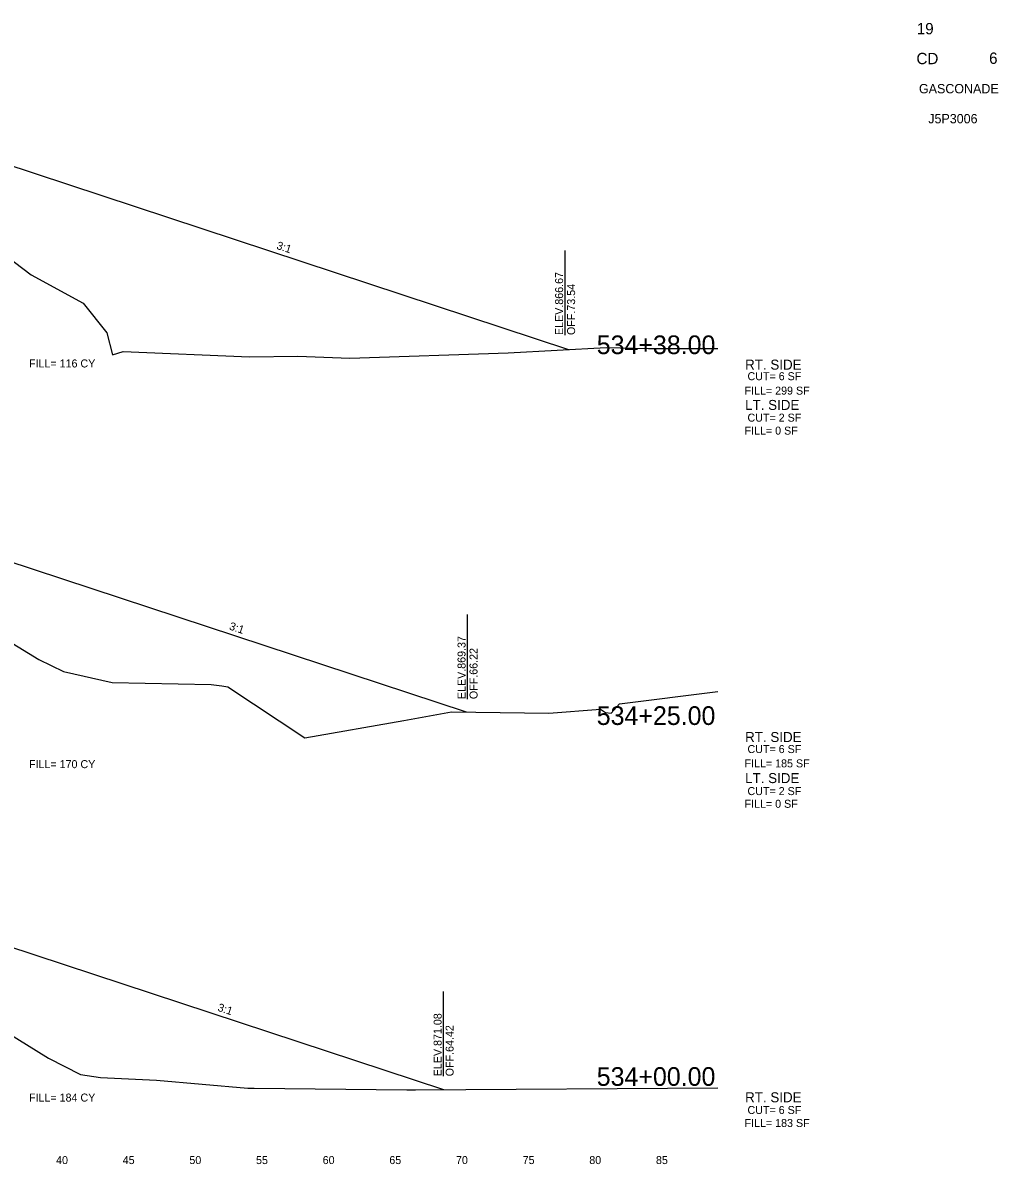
# Model space of a CAD drawing. Extents: x -4 to 359, y 0 to 1436.
# Drawn here: x 81 to 154.2, y 750.5 to 836.1 of the extents above; entities that cross this region are included whole.
import ezdxf

# ---------------------------------------------------------------- set-up
doc = ezdxf.new("R2010")
doc.units = 0
for name, color, linetype in [('Common-Title block info', 7, 'Continuous'), ('XS-Existing surface-ground', 7, 'Continuous'), ('XS-Proposed surface-ground', 7, 'Continuous'), ('XS-Text-ditch slope', 7, 'Continuous'), ('XS-Text-earthwork labels', 7, 'Continuous'), ('XS-Text-offset label', 7, 'Continuous'), ('XS-Text-profile report', 7, 'Continuous'), ('XS-Text-tie elevation', 7, 'Continuous'), ('XS-Text-tie offset', 7, 'Continuous')]:
    doc.layers.add(name, color=color, linetype=linetype)

msp = doc.modelspace()

# ---------------------------------------------------------------- linework, layer by layer
at = {"layer": 'XS-Existing surface-ground'}
for p, q in [((76.346, 821.105), (81.611, 817.179)), ((81.611, 817.179), (85.502, 815.044)), ((85.502, 815.044), (87.286, 812.818)), ((87.286, 812.818), (87.719, 811.17)), ((117.383, 811.308), (124.748, 811.723)), ((124.748, 811.723), (127.914, 811.633)), ((127.914, 811.633), (133.13, 811.634)), ((87.719, 811.17), (88.513, 811.42)), ((88.513, 811.42), (97.997, 811.011)), ((97.997, 811.011), (101.605, 811.078)), ((101.605, 811.078), (105.511, 810.922)), ((105.511, 810.922), (117.383, 811.308)), ((76.896, 791.548), (82.186, 788.316)), ((82.186, 788.316), (84.047, 787.406)), ((84.047, 787.406), (87.696, 786.585)), ((87.696, 786.585), (95.109, 786.45)), ((95.109, 786.45), (95.927, 786.35)), ((95.927, 786.35), (96.376, 786.272)), ((96.376, 786.272), (102.143, 782.455)), ((125.754, 785.002), (133.13, 785.912)), ((125.125, 784.286), (125.754, 785.002)), ((109.565, 783.737), (113.15, 784.398)), ((113.15, 784.398), (120.448, 784.284)), ((120.448, 784.284), (124.328, 784.604)), ((124.328, 784.604), (124.692, 784.349)), ((124.692, 784.349), (125.125, 784.286)), ((102.143, 782.455), (109.565, 783.737)), ((77.571, 761.715), (82.923, 758.416)), ((82.923, 758.416), (85.311, 757.202)), ((85.311, 757.202), (86.823, 756.97)), ((86.823, 756.97), (91.009, 756.771)), ((91.009, 756.771), (97.857, 756.162)), ((97.857, 756.162), (98.333, 756.171)), ((98.333, 756.171), (109.804, 756.046)), ((109.804, 756.046), (110.456, 756.045)), ((110.456, 756.045), (133.13, 756.197))]:
    msp.add_line(p, q, dxfattribs=at)
at = {"layer": 'XS-Proposed surface-ground'}
for points in [[(79.416, 825.593), (121.928, 811.564)], [(79.64, 795.8), (114.242, 784.381)], [(79.699, 766.901), (112.553, 756.059)]]:
    msp.add_lwpolyline(points, dxfattribs=at)
at = {"layer": 'XS-Text-tie offset'}
for p, q in [((121.666, 812.651), (121.666, 819.001)), ((114.348, 785.346), (114.348, 791.696)), ((112.553, 757.059), (112.553, 763.409))]:
    msp.add_line(p, q, dxfattribs=at)

# ---------------------------------------------------------------- texts
at = {"layer": 'Common-Title block info'}
for s, height, p in [('19', 0.85, (148.047, 835.203)), ('CD', 0.85, (148.025, 832.965)), ('6', 0.85, (153.472, 832.988)), ('GASCONADE', 0.7, (148.211, 830.778)), ('J5P3006', 0.7, (148.909, 828.528))]:
    msp.add_text(s, height=height, dxfattribs=at).set_placement(p)
at = {"layer": 'XS-Text-ditch slope'}
for p in [(99.97, 819.126), (96.423, 790.578), (95.555, 761.984)]:
    msp.add_text('3:1', height=0.6, rotation=341.73711, dxfattribs=at).set_placement(p)
at = {"layer": 'XS-Text-earthwork labels'}
for s, height, p in [('FILL= 116 CY           ', 0.6, (81.452, 810.221)), ('RT. SIDE', 0.75, (135.171, 810.058)), (' CUT= 6 SF           ', 0.6, (135.125, 809.264)), ('FILL= 299 SF           ', 0.6, (135.125, 808.182)), ('LT. SIDE', 0.75, (135.171, 807.034)), (' CUT= 2 SF           ', 0.6, (135.125, 806.157)), ('FILL= 0 SF           ', 0.6, (135.125, 805.183)), ('RT. SIDE', 0.75, (135.171, 782.129)), (' CUT= 6 SF           ', 0.6, (135.125, 781.301)), ('FILL= 170 CY           ', 0.6, (81.452, 780.17)), ('FILL= 185 SF           ', 0.6, (135.125, 780.227)), ('LT. SIDE', 0.75, (135.171, 779.048)), (' CUT= 2 SF           ', 0.6, (135.125, 778.149)), ('FILL= 0 SF           ', 0.6, (135.125, 777.197)), ('RT. SIDE', 0.75, (135.171, 755.111)), ('FILL= 184 CY           ', 0.6, (81.452, 755.164)), (' CUT= 6 SF           ', 0.6, (135.125, 754.233)), ('FILL= 183 SF           ', 0.6, (135.125, 753.258))]:
    msp.add_text(s, height=height, dxfattribs=at).set_placement(p)
at = {"layer": 'XS-Text-offset label'}
for s, height, p in [('           534+38.00           ', 1.4, (118.317, 811.221)), ('           534+25.00           ', 1.4, (118.317, 783.409)), ('           534+00.00           ', 1.4, (118.317, 756.344)), ('           40           ', 0.6, (81.03, 750.477)), ('           45           ', 0.6, (86.03, 750.477)), ('           50           ', 0.6, (91.03, 750.477)), ('           55           ', 0.6, (96.03, 750.477)), ('           60           ', 0.6, (101.03, 750.477)), ('           65           ', 0.6, (106.03, 750.477)), ('           70           ', 0.6, (111.03, 750.477)), ('           75           ', 0.6, (116.03, 750.477)), ('           80           ', 0.6, (121.03, 750.477)), ('           85           ', 0.6, (126.03, 750.477))]:
    msp.add_text(s, height=height, dxfattribs=at).set_placement(p)
at = {"layer": 'XS-Text-profile report'}
for s, p in [('Rt_Agg_Layer_1_B13', (82.896, 824.439)), ('Fill_Slope_2_B1', (121.916, 811.564)), ('Rt_Agg_Layer_1_B13', (83.12, 794.646)), ('Fill_Slope_2_B1', (114.23, 784.38)), ('Rt_Agg_Layer_1_B13', (83.179, 765.747)), ('Fill_Slope_2_B1', (112.541, 756.058))]:
    msp.add_text(s, height=0.00167, dxfattribs=at).set_placement(p)
at = {"layer": 'XS-Text-tie elevation'}
for s, p in [('ELEV.866.67', (121.516, 812.651)), ('OFF.73.54', (122.416, 812.651)), ('ELEV.869.37', (114.198, 785.346)), ('OFF.66.22', (115.098, 785.346)), ('ELEV.871.08', (112.403, 757.059)), ('OFF.64.42', (113.303, 757.059))]:
    msp.add_text(s, height=0.6, rotation=90, dxfattribs=at).set_placement(p)

doc.saveas('drawing.dxf')
